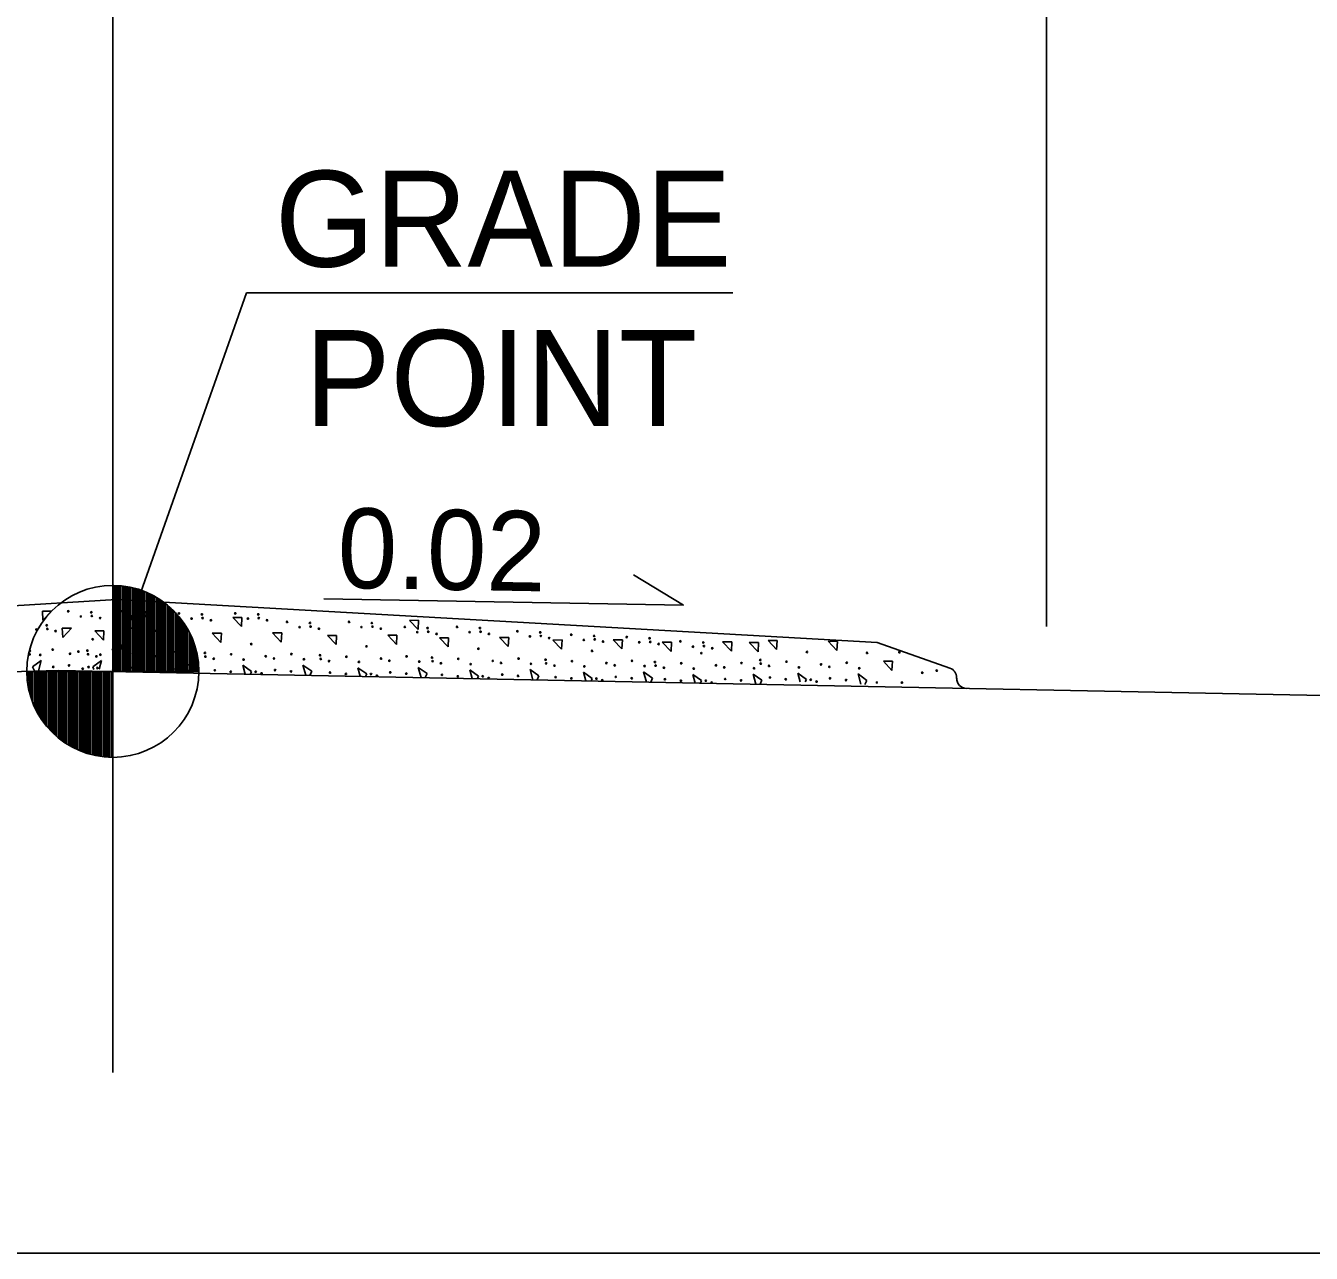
# Model space of a CAD drawing. Extents: x 1904401 to 1905163, y 193929 to 194736.
# Drawn here: x 1904579.35 to 1904591.41, y 194429.04 to 194440.55 of the extents above; entities that cross this region are included whole.
import ezdxf

# ---------------------------------------------------------------- set-up
doc = ezdxf.new("R2010")
doc.units = 0
for name, color, linetype in [('Prop Dimension', 7, 'Continuous'), ('Prop Dimension Text', 7, 'Continuous'), ('Typical Arrow Superelevation CELL', 7, 'Continuous'), ('Typical Curb CELL', 7, 'Continuous'), ('Typical Grade Point Symbol CELL', 7, 'Continuous'), ('Typical Pavement Slope CELL', 7, 'Continuous'), ('Typical Sidewalk and Rail CELL', 7, 'Continuous'), ('Typical Text Grade Point CELL', 7, 'Continuous')]:
    doc.layers.add(name, color=color, linetype=linetype)

msp = doc.modelspace()

# ---------------------------------------------------------------- linework, layer by layer
at = {"layer": 'Prop Dimension'}
for p, q in [((1904588.922, 194451.454), (1904588.922, 194434.915)), ((1904580.172, 194430.732), (1904580.172, 194448.437))]:
    msp.add_line(p, q, dxfattribs=at)
at = {"layer": 'Typical Arrow Superelevation CELL'}
for q in [(1904585.052, 194435.399), (1904582.148, 194435.175)]:
    msp.add_line((1904585.522, 194435.116), q, dxfattribs=at)
at = {"layer": 'Typical Curb CELL'}
for p, q in [((1904572.916, 194434.729), (1904580.206, 194435.168)), ((1904587.336, 194434.764), (1904580.206, 194435.168)), ((1904579.511, 194435.059), (1904579.597, 194435.059)), ((1904579.516, 194434.973), (1904579.511, 194435.059)), ((1904579.597, 194435.059), (1904579.516, 194434.973)), ((1904581.381, 194435), (1904581.295, 194435)), ((1904581.295, 194435), (1904581.376, 194434.914)), ((1904581.376, 194434.914), (1904581.381, 194435)), ((1904583.037, 194434.973), (1904582.951, 194434.972)), ((1904582.951, 194434.972), (1904583.032, 194434.887)), ((1904583.032, 194434.887), (1904583.037, 194434.973)), ((1904579.697, 194434.898), (1904579.783, 194434.898)), ((1904579.702, 194434.812), (1904579.697, 194434.898)), ((1904579.783, 194434.898), (1904579.702, 194434.812)), ((1904580.088, 194434.874), (1904580.002, 194434.874)), ((1904580.002, 194434.874), (1904580.083, 194434.788)), ((1904580.083, 194434.788), (1904580.088, 194434.874)), ((1904580.262, 194434.9), (1904580.348, 194434.9)), ((1904580.267, 194434.813), (1904580.262, 194434.9)), ((1904580.348, 194434.9), (1904580.267, 194434.813)), ((1904580.653, 194434.877), (1904580.567, 194434.877)), ((1904580.567, 194434.877), (1904580.648, 194434.791)), ((1904580.648, 194434.791), (1904580.653, 194434.877)), ((1904581.189, 194434.852), (1904581.103, 194434.852)), ((1904581.103, 194434.852), (1904581.184, 194434.766)), ((1904581.184, 194434.766), (1904581.189, 194434.852)), ((1904581.754, 194434.855), (1904581.668, 194434.855)), ((1904581.668, 194434.855), (1904581.749, 194434.769)), ((1904581.749, 194434.769), (1904581.754, 194434.855)), ((1904582.269, 194434.831), (1904582.183, 194434.83)), ((1904582.183, 194434.83), (1904582.265, 194434.745)), ((1904582.265, 194434.745), (1904582.269, 194434.831)), ((1904582.834, 194434.834), (1904582.748, 194434.833)), ((1904582.748, 194434.833), (1904582.83, 194434.747)), ((1904582.83, 194434.747), (1904582.834, 194434.834)), ((1904583.318, 194434.81), (1904583.232, 194434.809)), ((1904583.232, 194434.809), (1904583.313, 194434.724)), ((1904583.313, 194434.724), (1904583.318, 194434.81)), ((1904583.883, 194434.813), (1904583.797, 194434.812)), ((1904583.797, 194434.812), (1904583.878, 194434.726)), ((1904583.878, 194434.726), (1904583.883, 194434.813)), ((1904584.948, 194434.791), (1904584.862, 194434.791)), ((1904584.862, 194434.791), (1904584.943, 194434.705)), ((1904584.943, 194434.705), (1904584.948, 194434.791)), ((1904584.383, 194434.789), (1904584.297, 194434.788)), ((1904584.297, 194434.788), (1904584.378, 194434.702)), ((1904584.378, 194434.702), (1904584.383, 194434.789)), ((1904585.408, 194434.768), (1904585.322, 194434.768)), ((1904585.322, 194434.768), (1904585.404, 194434.682)), ((1904585.404, 194434.682), (1904585.408, 194434.768)), ((1904585.973, 194434.771), (1904585.887, 194434.77)), ((1904585.887, 194434.77), (1904585.969, 194434.685)), ((1904585.969, 194434.685), (1904585.973, 194434.771)), ((1904586.224, 194434.765), (1904586.137, 194434.765)), ((1904586.137, 194434.765), (1904586.219, 194434.679)), ((1904586.219, 194434.679), (1904586.224, 194434.765)), ((1904586.399, 194434.784), (1904586.313, 194434.785)), ((1904586.313, 194434.785), (1904586.393, 194434.698)), ((1904586.393, 194434.698), (1904586.399, 194434.784)), ((1904586.964, 194434.775), (1904586.878, 194434.777)), ((1904586.878, 194434.777), (1904586.958, 194434.689)), ((1904586.958, 194434.689), (1904586.964, 194434.775)), ((1904588.018, 194434.525), (1904587.336, 194434.764)), ((1904579.418, 194434.536), (1904579.5, 194434.595)), ((1904579.5, 194434.595), (1904579.473, 194434.499)), ((1904579.983, 194434.538), (1904580.065, 194434.596)), ((1904580.065, 194434.596), (1904580.042, 194434.515)), ((1904580.287, 194434.573), (1904580.31, 194434.491)), ((1904580.37, 194434.515), (1904580.287, 194434.573)), ((1904580.852, 194434.575), (1904580.879, 194434.48)), ((1904580.935, 194434.517), (1904580.852, 194434.575)), ((1904581.388, 194434.551), (1904581.411, 194434.469)), ((1904581.47, 194434.493), (1904581.388, 194434.551)), ((1904581.953, 194434.553), (1904581.98, 194434.458)), ((1904582.035, 194434.495), (1904581.953, 194434.553)), ((1904587.481, 194434.59), (1904587.395, 194434.591)), ((1904587.395, 194434.591), (1904587.474, 194434.504)), ((1904587.474, 194434.504), (1904587.481, 194434.59)), ((1904579.435, 194434.498), (1904579.418, 194434.536)), ((1904579.993, 194434.513), (1904579.983, 194434.538)), ((1904580.359, 194434.49), (1904580.37, 194434.515)), ((1904580.918, 194434.479), (1904580.935, 194434.517)), ((1904581.46, 194434.468), (1904581.47, 194434.493)), ((1904582.019, 194434.457), (1904582.035, 194434.495)), ((1904582.468, 194434.529), (1904582.491, 194434.448)), ((1904582.551, 194434.471), (1904582.468, 194434.529)), ((1904582.54, 194434.447), (1904582.551, 194434.471)), ((1904583.033, 194434.532), (1904583.06, 194434.436)), ((1904583.116, 194434.474), (1904583.033, 194434.532)), ((1904583.099, 194434.436), (1904583.116, 194434.474)), ((1904583.517, 194434.508), (1904583.54, 194434.427)), ((1904583.599, 194434.45), (1904583.517, 194434.508)), ((1904583.589, 194434.426), (1904583.599, 194434.45)), ((1904584.082, 194434.511), (1904584.109, 194434.415)), ((1904584.164, 194434.453), (1904584.082, 194434.511)), ((1904584.148, 194434.415), (1904584.164, 194434.453)), ((1904584.582, 194434.487), (1904584.605, 194434.405)), ((1904584.664, 194434.429), (1904584.582, 194434.487)), ((1904585.147, 194434.489), (1904585.174, 194434.394)), ((1904585.229, 194434.431), (1904585.147, 194434.489)), ((1904585.213, 194434.393), (1904585.229, 194434.431)), ((1904585.608, 194434.466), (1904585.631, 194434.385)), ((1904585.69, 194434.408), (1904585.608, 194434.466)), ((1904586.173, 194434.469), (1904586.2, 194434.374)), ((1904586.255, 194434.411), (1904586.173, 194434.469)), ((1904586.592, 194434.478), (1904586.614, 194434.396)), ((1904586.674, 194434.419), (1904586.592, 194434.478)), ((1904587.157, 194434.47), (1904587.182, 194434.374)), ((1904587.238, 194434.41), (1904587.157, 194434.47)), ((1904588.081, 194434.429), (1904588.081, 194434.435)), ((1904584.654, 194434.404), (1904584.664, 194434.429)), ((1904585.679, 194434.384), (1904585.69, 194434.408)), ((1904586.238, 194434.373), (1904586.255, 194434.411)), ((1904586.662, 194434.395), (1904586.674, 194434.419)), ((1904587.221, 194434.372), (1904587.238, 194434.41))]:
    msp.add_line(p, q, dxfattribs=at)
for centre in [(1904579.753, 194435.058), (1904579.968, 194435.048), (1904580.259, 194435.058), (1904580.474, 194435.048), (1904580.791, 194435.038), (1904581.006, 194435.028), (1904581.319, 194435.038), (1904581.534, 194435.028), (1904579.551, 194434.926), (1904579.871, 194435.009), (1904579.974, 194435.014), (1904580.052, 194434.994), (1904580.377, 194435.009), (1904580.479, 194435.014), (1904580.557, 194434.994), (1904580.909, 194434.989), (1904581.012, 194434.994), (1904581.09, 194434.974), (1904581.437, 194434.989), (1904581.539, 194434.994), (1904581.617, 194434.974), (1904581.804, 194434.958), (1904581.922, 194434.909), (1904582.019, 194434.948), (1904582.025, 194434.914), (1904582.385, 194434.958), (1904582.502, 194434.909), (1904582.599, 194434.948), (1904582.605, 194434.914), (1904582.908, 194434.911), (1904583.398, 194434.911), (1904579.454, 194434.887), (1904579.557, 194434.892), (1904579.634, 194434.872), (1904579.982, 194434.795), (1904582.103, 194434.894), (1904582.683, 194434.894), (1904583.025, 194434.862), (1904583.122, 194434.9), (1904583.128, 194434.866), (1904583.206, 194434.846), (1904583.515, 194434.862), (1904583.612, 194434.9), (1904583.618, 194434.866), (1904583.696, 194434.846), (1904583.963, 194434.871), (1904584.081, 194434.822), (1904584.178, 194434.86), (1904584.183, 194434.826), (1904584.261, 194434.806), (1904584.468, 194434.838), (1904584.586, 194434.789), (1904584.683, 194434.827), (1904584.689, 194434.794), (1904584.989, 194434.816), (1904585.203, 194434.805), (1904579.396, 194434.687), (1904579.607, 194434.699), (1904579.848, 194434.68), (1904579.933, 194434.689), (1904580.172, 194434.701), (1904580.179, 194434.676), (1904580.368, 194434.772), (1904580.413, 194434.681), (1904580.418, 194434.715), (1904580.744, 194434.679), (1904581.034, 194434.667), (1904581.469, 194434.75), (1904582.549, 194434.728), (1904583.598, 194434.707), (1904584.663, 194434.686), (1904584.767, 194434.774), (1904585.106, 194434.767), (1904585.209, 194434.771), (1904585.287, 194434.751), (1904585.491, 194434.776), (1904585.609, 194434.726), (1904585.689, 194434.665), (1904585.706, 194434.765), (1904585.712, 194434.731), (1904585.79, 194434.711), (1904586.677, 194434.676), (1904587.242, 194434.667), (1904587.545, 194434.674), (1904579.391, 194434.653), (1904579.49, 194434.649), (1904579.761, 194434.55), (1904579.77, 194434.659), (1904579.939, 194434.655), (1904580.017, 194434.635), (1904580.055, 194434.651), (1904580.297, 194434.627), (1904580.326, 194434.552), (1904580.335, 194434.66), (1904580.504, 194434.658), (1904580.582, 194434.637), (1904580.862, 194434.63), (1904581.039, 194434.633), (1904581.117, 194434.613), (1904581.28, 194434.654), (1904581.397, 194434.605), (1904581.604, 194434.636), (1904581.682, 194434.615), (1904581.845, 194434.657), (1904581.962, 194434.608), (1904582.114, 194434.645), (1904582.12, 194434.611), (1904582.198, 194434.591), (1904582.36, 194434.632), (1904582.478, 194434.583), (1904582.685, 194434.614), (1904582.763, 194434.594), (1904582.925, 194434.635), (1904583.043, 194434.586), (1904583.163, 194434.624), (1904583.168, 194434.59), (1904583.246, 194434.57), (1904583.409, 194434.612), (1904583.526, 194434.562), (1904583.733, 194434.593), (1904583.811, 194434.573), (1904583.974, 194434.614), (1904584.091, 194434.565), (1904584.228, 194434.603), (1904584.233, 194434.569), (1904584.311, 194434.549), (1904584.474, 194434.59), (1904584.798, 194434.572), (1904584.876, 194434.551), (1904585.039, 194434.593), (1904585.156, 194434.544), (1904585.253, 194434.582), (1904585.259, 194434.548), (1904585.499, 194434.57), (1904585.824, 194434.551), (1904586.064, 194434.572), (1904586.24, 194434.601), (1904586.245, 194434.567), (1904586.323, 194434.546), (1904586.486, 194434.584), (1904586.81, 194434.559), (1904587.051, 194434.575), (1904579.612, 194434.536), (1904579.888, 194434.519), (1904579.943, 194434.535), (1904580.026, 194434.526), (1904580.175, 194434.513), (1904580.177, 194434.538), (1904580.409, 194434.513), (1904580.464, 194434.497), (1904580.591, 194434.529), (1904580.74, 194434.516), (1904581.127, 194434.504), (1904581.276, 194434.491), (1904581.51, 194434.491), (1904581.565, 194434.475), (1904581.692, 194434.507), (1904581.841, 194434.494), (1904582.207, 194434.483), (1904582.356, 194434.47), (1904582.591, 194434.469), (1904582.646, 194434.453), (1904582.772, 194434.485), (1904582.921, 194434.473), (1904583.256, 194434.462), (1904583.405, 194434.449), (1904583.639, 194434.448), (1904583.694, 194434.432), (1904583.821, 194434.464), (1904583.97, 194434.452), (1904584.321, 194434.44), (1904584.47, 194434.428), (1904584.591, 194434.541), (1904584.704, 194434.427), (1904584.886, 194434.443), (1904585.035, 194434.43), (1904585.337, 194434.528), (1904585.617, 194434.521), (1904585.902, 194434.531), (1904586.182, 194434.523), (1904586.33, 194434.437), (1904586.603, 194434.532), (1904586.888, 194434.537), (1904586.895, 194434.429), (1904587.168, 194434.524), (1904587.759, 194434.481), (1904587.895, 194434.502), (1904584.759, 194434.411), (1904585.346, 194434.42), (1904585.496, 194434.407), (1904585.73, 194434.406), (1904585.785, 194434.39), (1904585.911, 194434.423), (1904586.06, 194434.41), (1904586.479, 194434.421), (1904586.713, 194434.416), (1904586.768, 194434.399), (1904587.044, 194434.413), (1904587.333, 194434.39), (1904587.568, 194434.389)]:
    msp.add_circle(centre, 0.00635, dxfattribs=at)
for centre, start, end in [((1904587.987, 194434.436), 359.1262, 70.6912), ((1904588.175, 194434.428), 179.1262, 269.1262)]:
    msp.add_arc(centre, 0.0937, start, end, dxfattribs=at)
at = {"layer": 'Typical Grade Point Symbol CELL'}
for p, q in [((1904580.172, 194434.494), (1904580.172, 194435.3)), ((1904579.367, 194434.494), (1904580.172, 194434.494)), ((1904580.17, 194433.688), (1904580.172, 194434.494)), ((1904580.172, 194434.494), (1904580.17, 194433.688)), ((1904580.978, 194434.494), (1904580.172, 194434.494))]:
    msp.add_line(p, q, dxfattribs=at)
for points in [[(1904580.179, 194435.3), (1904580.179, 194435.3), (1904580.179, 194434.494)], [(1904580.196, 194435.3), (1904580.196, 194434.494)], [(1904580.212, 194435.298), (1904580.212, 194434.494)], [(1904580.228, 194435.298), (1904580.228, 194434.494)], [(1904580.244, 194435.296), (1904580.244, 194434.494)], [(1904580.26, 194435.294), (1904580.26, 194434.494)], [(1904580.276, 194435.293), (1904580.276, 194434.494)], [(1904580.292, 194435.291), (1904580.292, 194434.494)], [(1904580.308, 194435.289), (1904580.308, 194434.494)], [(1904580.324, 194435.285), (1904580.324, 194434.494)], [(1904580.341, 194435.282), (1904580.341, 194434.494)], [(1904580.357, 194435.278), (1904580.357, 194434.494)], [(1904580.373, 194435.275), (1904580.373, 194434.494)], [(1904580.389, 194435.269), (1904580.389, 194434.494)], [(1904580.405, 194435.266), (1904580.405, 194434.494)], [(1904580.421, 194435.26), (1904580.421, 194434.494)], [(1904580.437, 194435.255), (1904580.437, 194434.494)], [(1904580.453, 194435.25), (1904580.453, 194434.494)], [(1904580.469, 194435.242), (1904580.469, 194434.494)], [(1904580.486, 194435.235), (1904580.486, 194434.494)], [(1904580.502, 194435.228), (1904580.502, 194434.494)], [(1904580.518, 194435.221), (1904580.518, 194434.494)], [(1904580.534, 194435.214), (1904580.534, 194434.494)], [(1904580.55, 194435.205), (1904580.55, 194434.494)], [(1904580.566, 194435.196), (1904580.566, 194434.494)], [(1904580.582, 194435.187), (1904580.582, 194434.494)], [(1904580.598, 194435.178), (1904580.598, 194434.494)], [(1904580.615, 194435.167), (1904580.615, 194434.494)], [(1904580.631, 194435.157), (1904580.631, 194434.494)], [(1904580.647, 194435.144), (1904580.647, 194434.494)], [(1904580.663, 194435.133), (1904580.663, 194434.494)], [(1904580.679, 194435.121), (1904580.679, 194434.494)], [(1904580.695, 194435.106), (1904580.695, 194434.494)], [(1904580.711, 194435.092), (1904580.711, 194434.494)], [(1904580.727, 194435.078), (1904580.727, 194434.494)], [(1904580.743, 194435.062), (1904580.743, 194434.494)], [(1904580.76, 194435.046), (1904580.76, 194434.494)], [(1904580.776, 194435.028), (1904580.776, 194434.494)], [(1904580.792, 194435.008), (1904580.792, 194434.494)], [(1904580.808, 194434.988), (1904580.808, 194434.494)], [(1904580.824, 194434.967), (1904580.824, 194434.494)], [(1904580.84, 194434.943), (1904580.84, 194434.494)], [(1904580.856, 194434.918), (1904580.856, 194434.494)], [(1904580.872, 194434.892), (1904580.872, 194434.494)], [(1904580.888, 194434.863), (1904580.888, 194434.494)], [(1904580.905, 194434.829), (1904580.905, 194434.494)], [(1904580.921, 194434.791), (1904580.921, 194434.494)], [(1904580.937, 194434.747), (1904580.937, 194434.494)], [(1904580.953, 194434.691), (1904580.953, 194434.494)], [(1904580.969, 194434.609), (1904580.969, 194434.494)], [(1904579.37, 194434.494), (1904579.37, 194434.406)], [(1904579.386, 194434.494), (1904579.386, 194434.311)], [(1904579.402, 194434.494), (1904579.402, 194434.254)], [(1904579.419, 194434.494), (1904579.419, 194434.206)], [(1904579.435, 194434.494), (1904579.435, 194434.168)], [(1904579.451, 194434.494), (1904579.451, 194434.134)], [(1904579.467, 194434.494), (1904579.467, 194434.104)], [(1904579.483, 194434.494), (1904579.483, 194434.075)], [(1904579.499, 194434.494), (1904579.499, 194434.05)], [(1904579.515, 194434.494), (1904579.515, 194434.027)], [(1904579.531, 194434.494), (1904579.531, 194434.005)], [(1904579.547, 194434.494), (1904579.547, 194433.986)], [(1904579.564, 194434.494), (1904579.564, 194433.966)], [(1904579.58, 194434.494), (1904579.58, 194433.948)], [(1904579.596, 194434.494), (1904579.596, 194433.93)], [(1904579.612, 194434.494), (1904579.612, 194433.914)], [(1904579.628, 194434.494), (1904579.628, 194433.9)], [(1904579.644, 194434.494), (1904579.644, 194433.885)], [(1904579.66, 194434.494), (1904579.66, 194433.871)], [(1904579.676, 194434.494), (1904579.676, 194433.859)], [(1904579.693, 194434.494), (1904579.693, 194433.846)], [(1904579.709, 194434.494), (1904579.709, 194433.835)], [(1904579.725, 194434.494), (1904579.725, 194433.825)], [(1904579.741, 194434.494), (1904579.741, 194433.814)], [(1904579.757, 194434.494), (1904579.757, 194433.803)], [(1904579.773, 194434.494), (1904579.773, 194433.794)], [(1904579.789, 194434.494), (1904579.789, 194433.785)], [(1904579.805, 194434.494), (1904579.805, 194433.776)], [(1904579.821, 194434.494), (1904579.821, 194433.769)], [(1904579.838, 194434.494), (1904579.838, 194433.762)], [(1904579.854, 194434.494), (1904579.854, 194433.755)], [(1904579.87, 194434.494), (1904579.87, 194433.748)], [(1904579.886, 194434.494), (1904579.886, 194433.74)], [(1904579.902, 194434.494), (1904579.902, 194433.735)], [(1904579.918, 194434.494), (1904579.918, 194433.73)], [(1904579.934, 194434.494), (1904579.934, 194433.724)], [(1904579.95, 194434.494), (1904579.95, 194433.721)], [(1904579.966, 194434.494), (1904579.966, 194433.715)], [(1904579.983, 194434.494), (1904579.983, 194433.712)], [(1904579.999, 194434.494), (1904579.999, 194433.708)], [(1904580.015, 194434.494), (1904580.015, 194433.705)], [(1904580.031, 194434.494), (1904580.031, 194433.701)], [(1904580.047, 194434.494), (1904580.047, 194433.699)], [(1904580.063, 194434.494), (1904580.063, 194433.696)], [(1904580.079, 194434.494), (1904580.079, 194433.694)], [(1904580.095, 194434.494), (1904580.095, 194433.692)], [(1904580.111, 194434.494), (1904580.111, 194433.69)], [(1904580.128, 194434.494), (1904580.128, 194433.69)], [(1904580.144, 194434.494), (1904580.144, 194433.688)], [(1904580.16, 194434.494), (1904580.16, 194433.688), (1904580.16, 194433.688)]]:
    msp.add_lwpolyline(points, dxfattribs=at)
msp.add_circle((1904580.171, 194434.494), 0.806, dxfattribs=at)
for start, end in [(359.9905, 89.9905), (179.9905, 269.9905)]:
    msp.add_arc((1904580.171, 194434.494), 0.806, start, end, dxfattribs=at)
at = {"layer": 'Typical Pavement Slope CELL'}
for p, q in [((1904579.661, 194434.504), (1904557.583, 194433.898)), ((1904602.762, 194434.042), (1904579.661, 194434.504))]:
    msp.add_line(p, q, dxfattribs=at)
at = {"layer": 'Typical Sidewalk and Rail CELL'}
msp.add_line((1904550.75, 194429.038), (1904609.594, 194429.038), dxfattribs=at)
at = {"layer": 'Typical Text Grade Point CELL'}
for p, q in [((1904580.172, 194434.494), (1904581.424, 194438.043)), ((1904581.424, 194438.043), (1904585.982, 194438.043))]:
    msp.add_line(p, q, dxfattribs=at)

# ---------------------------------------------------------------- texts
at = {"layer": 'Prop Dimension Text'}
for s, p in [('GRADE', (1904581.69, 194438.288)), ('POINT', (1904581.971, 194436.794))]:
    msp.add_text(s, height=0.9, dxfattribs=at).set_placement(p)
msp.add_text('0.02', height=0.7499, rotation=359.0035, dxfattribs=at).set_placement((1904582.273, 194435.278))

doc.saveas('drawing.dxf')
